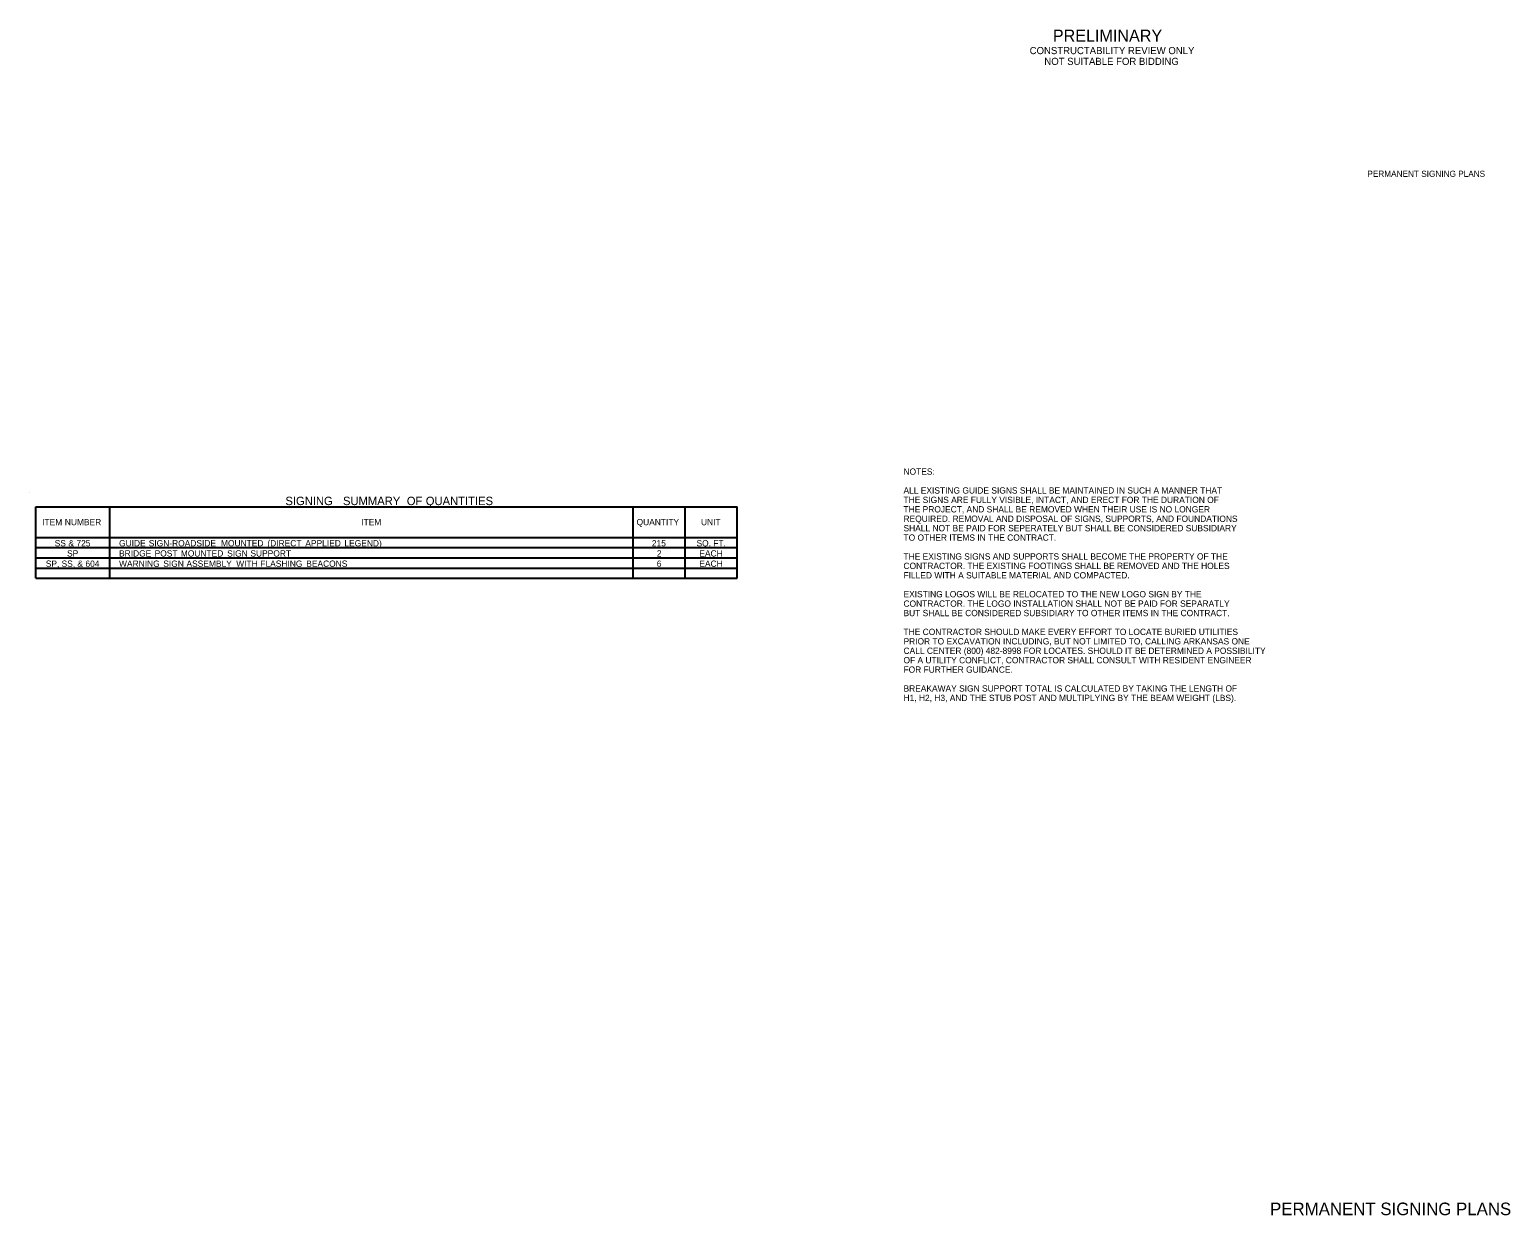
# Model space of a CAD drawing. Extents: x 229 to 4210, y 35 to 1715.
# Drawn here: x 229 to 1642, y 35 to 1167 of the extents above; entities that cross this region are included whole.
import ezdxf

# ---------------------------------------------------------------- set-up
doc = ezdxf.new("R2010")
doc.units = 0
for name, color, linetype in [('B_Concrete', 7, 'Continuous'), ('B_Concrete hidden', 7, 'Continuous'), ('B_Steel', 7, 'Continuous'), ('B_Steel Hidden', 7, 'Continuous'), ('Default', 7, 'Continuous')]:
    doc.layers.add(name, color=color, linetype=linetype)

msp = doc.modelspace()

# ---------------------------------------------------------------- linework, layer by layer
at = {"layer": 'B_Steel Hidden'}
msp.add_line((229.2, 725), (229.2, 725), dxfattribs=at)
at = {"layer": 'Default'}
for p, q in [((235, 711.3), (904.4, 711.3)), ((235, 711.3), (904.4, 711.3)), ((235, 643.1), (235, 711.3)), ((235, 643.1), (235, 711.3)), ((305.7, 643.1), (305.7, 711.3)), ((804.9, 643.1), (804.9, 711.3)), ((854.6, 643.1), (854.6, 711.3)), ((854.6, 643.1), (854.6, 711.3)), ((904.4, 643.1), (904.4, 711.3)), ((235, 682.1), (904.4, 682.1)), ((235, 682.1), (904.4, 682.1)), ((305.7, 643.1), (305.7, 682.1)), ((804.9, 672.3), (804.9, 682.1)), ((235, 672.3), (904.4, 672.3)), ((235, 662.6), (904.4, 662.6)), ((235, 652.8), (904.4, 652.8)), ((804.9, 643.1), (804.9, 662.6)), ((904.4, 643.1), (904.4, 652.8)), ((235, 643.1), (904.4, 643.1))]:
    msp.add_line(p, q, dxfattribs=at)

# ---------------------------------------------------------------- texts
at = {"layer": 'B_Concrete'}
msp.add_text('PERMANENT SIGNING PLANS', height=5.862, dxfattribs=at).set_placement((1505.6, 1026.2))
at = {"layer": 'B_Concrete hidden'}
for s, height, p in [('PRELIMINARY', 11.508, (1205.5, 1155.2)), ('CONSTRUCTABILITY REVIEW ONLY', 6.823, (1183.4, 1143.3)), ('NOT SUITABLE FOR BIDDING', 6.823, (1197.4, 1133))]:
    msp.add_text(s, height=height, rotation=0, dxfattribs=at).set_placement(p)
for s, p in [('NOTES:', (1063, 741.9)), ('ALL EXISTING GUIDE SIGNS SHALL BE MAINTAINED IN SUCH A MANNER THAT', (1063, 723.9)), ('THE SIGNS ARE FULLY VISIBLE, INTACT, AND ERECT FOR THE DURATION OF', (1063, 714.9)), ('THE PROJECT, AND SHALL BE REMOVED WHEN THEIR USE IS NO LONGER', (1063, 705.9)), ('SHALL NOT BE PAID FOR SEPERATELY BUT SHALL BE CONSIDERED SUBSIDIARY', (1063, 687.9)), ('REQUIRED. REMOVAL AND DISPOSAL OF SIGNS, SUPPORTS, AND FOUNDATIONS', (1063, 696.9)), ('TO OTHER ITEMS IN THE CONTRACT.', (1063, 678.9)), ('THE EXISTING SIGNS AND SUPPORTS SHALL BECOME THE PROPERTY OF THE ', (1063, 660.9)), ('CONTRACTOR. THE EXISTING FOOTINGS SHALL BE REMOVED AND THE HOLES', (1063, 651.9)), ('FILLED WITH A SUITABLE MATERIAL AND COMPACTED.', (1063, 642.9)), ('CONTRACTOR. THE LOGO INSTALLATION SHALL NOT BE PAID FOR SEPARATLY', (1063, 615.9)), ('EXISTING LOGOS WILL BE RELOCATED TO THE NEW LOGO SIGN BY THE ', (1063, 624.9)), ('BUT SHALL BE CONSIDERED SUBSIDIARY TO OTHER ITEMS IN THE CONTRACT.', (1063, 606.9)), ('THE CONTRACTOR SHOULD MAKE EVERY EFFORT TO LOCATE BURIED UTILITIES', (1063, 588.9)), ('PRIOR TO EXCAVATION INCLUDING, BUT NOT LIMITED TO, CALLING ARKANSAS ONE', (1063, 579.9)), ('OF A UTILITY CONFLICT, CONTRACTOR SHALL CONSULT WITH RESIDENT ENGINEER', (1063, 561.9)), ('CALL CENTER (800) 482-8998 FOR LOCATES. SHOULD IT BE DETERMINED A POSSIBILITY', (1063, 570.9)), ('FOR FURTHER GUIDANCE.', (1063, 552.9)), ('BREAKAWAY SIGN SUPPORT TOTAL IS CALCULATED BY TAKING THE LENGTH OF', (1063, 534.9)), ('H1, H2, H3, AND THE STUB POST AND MULTIPLYING BY THE BEAM WEIGHT (LBS).', (1063, 525.9))]:
    msp.add_text(s, height=6, dxfattribs=at).set_placement(p)
at = {"layer": 'B_Steel'}
msp.add_text('PERMANENT SIGNING PLANS', height=12, rotation=360, dxfattribs=at).set_placement((1412.8, 35.2))
at = {"layer": 'Default'}
for s, height, p in [('                                          SIGNING', 8, (348.4, 712.9)), (' SUMMARY', 8, (525.2, 712.9)), (' OF', 8, (586.1, 712.9)), (' QUANTITIES', 8, (604.2, 712.9)), ('ITEM', 6, (241.1, 693.7)), (' NUMBER', 6, (260.5, 693.7)), ('ITEM', 6, (545.6, 693.7)), ('QUANTITY', 6, (808.3, 693.7)), ('UNIT', 6, (869.8, 693.7)), ('SS', 6, (253.1, 673.5)), (' &', 6, (263.9, 673.5)), (' 725', 6, (271.6, 673.5)), ('GUIDE', 6, (314.5, 673.5)), (' SIGN-ROADSIDE', 6, (340.6, 673.5)), (' MOUNTED', 6, (409.5, 673.5)), (' (DIRECT', 6, (453.8, 673.5)), (' APPLIED', 6, (490, 673.5)), (' LEGEND)', 6, (527.3, 673.5)), ('215', 6, (822.9, 673.5)), ('SQ.', 6, (865.5, 673.5)), (' FT.', 6, (879.3, 673.5)), ('SP', 6, (264.9, 663.8)), ('BRIDGE', 6, (314.5, 663.8)), (' POST', 6, (346.2, 663.8)), (' MOUNTED', 6, (371.2, 663.8)), (' SIGN', 6, (415.4, 663.8)), (' SUPPORT', 6, (437.6, 663.8)), ('2', 6, (827.7, 663.8)), ('EACH', 6, (868.2, 663.8)), ('SP,', 6, (244.6, 654)), (' SS,', 6, (257.4, 654)), (' &', 6, (272.5, 654)), (' 604', 6, (280.2, 654)), ('WARNING', 6, (314.5, 654)), (' SIGN', 6, (354.5, 654)), (' ASSEMBLY', 6, (376.6, 654)), (' WITH', 6, (424.1, 654)), (' FLASHING', 6, (447.1, 654)), (' BEACONS', 6, (490.9, 654)), ('6', 6, (827.6, 654)), ('EACH', 6, (868.2, 654))]:
    msp.add_text(s, height=height, dxfattribs=at).set_placement(p)

doc.saveas('drawing.dxf')
